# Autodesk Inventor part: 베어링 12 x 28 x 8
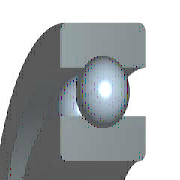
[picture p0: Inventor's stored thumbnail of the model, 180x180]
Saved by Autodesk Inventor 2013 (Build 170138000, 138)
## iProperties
IsCustomPart: 1
Created: 2012-02
Part Number: 베어링 12 x 28 x 8
Material: 강철, 연강
Description: 깊은 그루브 볼 베어링
Document SubType Name: Modeling
Standard: KS B 2023
Designer: mduedu
Standards Organization: KS
Language: ko-KR
Size Designation: 6001 - 12 x 28 x 8
Categories: <MemberInstance><Categories><Category DisplayName="샤프트 부품" InternalName="7f7aeb1f-a693-4053-b835-cee3144e0d98" Mnemonic="SHFT"><Category DisplayName="베어링" Inter
Density: 1 g/cm^3
Author: mduedu
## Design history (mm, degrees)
sketch "스케치" dims "d0" = 4.16 (= -0.26 x WD + 0.26 x BD)
  geometry: L1 (1.92, 10)-(6.08, 10); L2 (4, 10)-(4, 7.92); L3 (4, 10)-(4, 12.08); L4 (2.454, 8.608)-(0, 8.608); L5 (0, 6)-(8, 6); L6 (2.454, 11.392)-(0, 11.392); L7 (0, 14)-(8, 14); L8 (8, 6)-(8, 8.608); L9 (5.546, 8.608)-(8, 8.608); L10 (5.546, 11.392)-(8, 11.392); L11 (8, 14)-(8, 11.392); L12 (-1.4, 0)-(8.4, 0) reference; L13 (0, -0.3)-(0, 5.3) reference
  constraints: 22 end point, 4 point on line, 2 collinear, 2 perpendicular, 2 symmetric about line, 1 midpoint, 1 parallel, 14 other
  dimensions: "d9" = 12 diameter of L5 L12 (= WD); "d11" = 28 diameter of L7 L12 (= BD); "d12" = 8 distance between parallel lines of L8 L13 (= KB); "d13" = 17.216 diameter of L9 L12 (= 0.326 x BD + 0.674 x WD)
revolve "본체" stored, may be unused: angle "d6" = 90 deg
revolve "볼" stored, may be unused: angle "d7" = 90 deg
pattern_circular "IDS_ARRAYBALL[SIMPL:T]" dims angle "d3" = 360 deg
body "Solid1"
fillet "모깎기1" dims "d1" = 0.3 (= KRS)
other parameters: "WD" = 12 [user parameter; used in 5 equation terms], "BD" = 28 [user parameter; used in 5 equation terms], "KB" = 8 [user parameter; used in 1 equation term], "KRS" = 0.3 [user parameter; used in 1 equation term], "d4" = 0, "d5" = 0, "d8" = 0, "d14" = 0, "d15" = 0, "BBA" = 0 [user parameter], "BC0" = 2360000 [user parameter], "BC" = 5070000 [user parameter], "BR" = 14 (= 0.5 x BD) [user parameter], "WR" = 6 (= 0.5 x WD) [user parameter]
